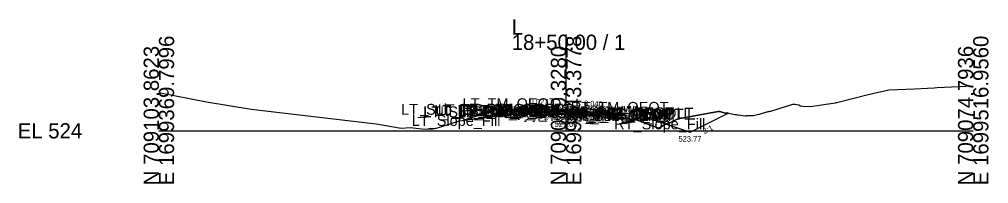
# Model space of a CAD drawing. Extents: x -63 to 1153, y -24 to 9522.
# Drawn here: x 974.3 to 1152.8, y 490.3 to 520.5 of the extents above; entities that cross this region are included whole.
import ezdxf

# ---------------------------------------------------------------- set-up
doc = ezdxf.new("R2010")
doc.units = 0
for name, color, linetype in [('Default', 7, 'Continuous'), ('Exist Cross Section Cell', 7, 'Continuous'), ('Exist XS Center Line Elevation Label', 7, 'Continuous'), ('Exist XS Ground Line', 7, 'Continuous'), ('Prop CMT DNC', 7, 'Continuous'), ('Prop CMT Pvmt Course 1', 7, 'Continuous'), ('Prop CMT Pvmt Course 2', 7, 'Continuous'), ('Prop CMT Pvmt Surface', 7, 'Continuous'), ('Prop CMT Pvmt Surface Overlay', 7, 'Continuous'), ('Prop CMT Pvmt Surface Shoulder', 7, 'Continuous'), ('Prop CMT Shld Paved Course 1', 7, 'Continuous'), ('Prop CMT Shld Paved Course 2', 7, 'Continuous'), ('Prop CMT Slope Grass', 7, 'Continuous'), ('Prop CMT Subgrade Earthwork', 7, 'Continuous'), ('Prop XS Ditch Standard Text', 7, 'Continuous'), ('Prop XS Earthwork Shape', 7, 'Continuous'), ('Prop XS EOT Tick Mark', 7, 'Continuous'), ('Prop XS SE Text', 7, 'Continuous'), ('Prop XS Side Slope Text', 7, 'Continuous')]:
    doc.layers.add(name, color=color, linetype=linetype)

msp = doc.modelspace()

# ---------------------------------------------------------------- linework, layer by layer
at = {"layer": 'Exist Cross Section Cell'}
for p, q in [((1075, 500), (1075, 517.67)), ((1000, 500), (1075, 500)), ((1075, 500), (1150, 500))]:
    msp.add_line(p, q, dxfattribs=at)
at = {"layer": 'Exist XS Ground Line'}
msp.add_lwpolyline([(1000, 507.05), (1008.75, 505.31), (1017.01, 503.98), (1040, 501.31), (1044.65, 500.47), (1046.27, 500.59), (1048.41, 500.39), (1050.28, 500.29), (1051.78, 500.66), (1055.36, 501.81), (1063.63, 502.9), (1064.17, 502.95), (1064.63, 503.02), (1064.89, 503.02), (1074.38, 503.08), (1074.84, 503.05), (1075, 503.03), (1083.86, 502.39), (1084.58, 502.31), (1088.01, 502), (1090.71, 500.95), (1092.1, 500.48), (1093.17, 501.19), (1094.23, 501.54), (1095.33, 502.06), (1095.52, 502.13), (1095.77, 502.2), (1095.96, 502.24), (1103.04, 503.52), (1103.27, 503.55), (1104.39, 503.22), (1104.68, 503.28), (1106.09, 503.02), (1106.31, 503), (1106.51, 502.96), (1106.7, 502.96), (1108.02, 502.77), (1108.11, 502.77), (1108.19, 502.77), (1108.26, 502.77), (1108.34, 502.79), (1109.45, 502.8), (1109.47, 502.8), (1109.49, 502.81), (1109.51, 502.81), (1110.51, 503.05), (1110.55, 503.06), (1110.58, 503.06), (1110.63, 503.07), (1111.96, 503.46), (1112.1, 503.49), (1112.25, 503.53), (1112.4, 503.56), (1112.56, 503.6), (1112.75, 503.63), (1116.8, 504.91), (1117.2, 504.87), (1117.54, 504.86), (1117.87, 504.75), (1118.21, 504.62), (1118.58, 504.53), (1118.91, 504.44), (1120.48, 504.53), (1122.07, 504.78), (1124.61, 505.16), (1124.72, 505.18), (1124.86, 505.21), (1130.43, 506.63), (1134.49, 507.55), (1139.19, 507.71), (1141.56, 507.85), (1142.81, 507.87), (1143.39, 507.98), (1150, 508.25)], dxfattribs=at)
at = {"layer": 'Prop CMT Pvmt Course 1'}
for points in [[(1075, 503.71), (1065, 503.98)], [(1065, 503.98), (1065, 503.73)], [(1065, 503.73), (1075, 503.46)], [(1075, 503.58), (1075, 503.71)], [(1075, 503.71), (1085, 503.31)], [(1075, 503.58), (1075, 503.71)], [(1075, 503.46), (1075, 503.58), (1075, 503.58)], [(1075, 503.46), (1075, 503.58), (1075, 503.58)], [(1085, 503.06), (1075, 503.46)], [(1085, 503.31), (1085, 503.06)]]:
    msp.add_lwpolyline(points, dxfattribs=at)
at = {"layer": 'Prop CMT Pvmt Course 2'}
for points in [[(1075, 503.46), (1065, 503.73)], [(1065, 503.73), (1065, 503.48)], [(1065, 503.48), (1075, 503.21)], [(1075, 503.21), (1075, 503.46)], [(1075, 503.21), (1075, 503.46)], [(1075, 503.46), (1085, 503.06)], [(1085, 502.81), (1075, 503.21)], [(1085, 503.06), (1085, 502.81)]]:
    msp.add_lwpolyline(points, dxfattribs=at)
at = {"layer": 'Prop CMT Pvmt Surface'}
for points in [[(1075, 503.71), (1065, 503.98)], [(1075, 503.71), (1085, 503.31)]]:
    msp.add_lwpolyline(points, dxfattribs=at)
at = {"layer": 'Prop CMT Pvmt Surface Overlay'}
for points in [[(1075, 503.71), (1065, 503.98)], [(1075, 503.71), (1085, 503.31)]]:
    msp.add_lwpolyline(points, dxfattribs=at)
at = {"layer": 'Prop CMT Pvmt Surface Shoulder'}
for points in [[(1065, 503.98), (1064.99, 503.98)], [(1085, 503.31), (1085.01, 503.31)]]:
    msp.add_lwpolyline(points, dxfattribs=at)
at = {"layer": 'Prop CMT Shld Paved Course 1'}
for points in [[(1065, 503.98), (1064.99, 503.98), (1064.75, 503.74)], [(1064.75, 503.74), (1065, 503.73)], [(1065, 503.73), (1065, 503.98)], [(1085, 503.31), (1085.01, 503.31), (1085.27, 503.04)], [(1085, 503.06), (1085, 503.31)], [(1085.27, 503.04), (1085, 503.06)]]:
    msp.add_lwpolyline(points, dxfattribs=at)
at = {"layer": 'Prop CMT Shld Paved Course 2'}
for points in [[(1064.75, 503.74), (1064.5, 503.49)], [(1064.5, 503.49), (1065, 503.48)], [(1065, 503.73), (1064.75, 503.74)], [(1064.75, 503.74), (1064.75, 503.74)], [(1065, 503.48), (1065, 503.73)], [(1085, 503.06), (1085.27, 503.04)], [(1085, 502.81), (1085, 503.06)], [(1085.53, 502.78), (1085, 502.81)], [(1085.27, 503.04), (1085.27, 503.04)], [(1085.27, 503.04), (1085.53, 502.78)]]:
    msp.add_lwpolyline(points, dxfattribs=at)
at = {"layer": 'Prop CMT Slope Grass'}
for points in [[(1062, 503.88), (1056.05, 501.9)], [(1064.99, 503.98), (1062, 503.88)], [(1085.01, 503.31), (1088, 503.07)], [(1088, 503.07), (1097.89, 499.77), (1104.84, 503.25)]]:
    msp.add_lwpolyline(points, dxfattribs=at)
at = {"layer": 'Prop CMT Subgrade Earthwork'}
for points in [[(1064.5, 503.49), (1064.05, 503.95)], [(1065, 503.48), (1064.5, 503.49)], [(1075, 503.21), (1065, 503.48)], [(1075, 503.21), (1085, 502.81)], [(1085, 502.81), (1085.53, 502.78)], [(1085.53, 502.78), (1085.97, 503.23)]]:
    msp.add_lwpolyline(points, dxfattribs=at)
at = {"layer": 'Prop XS Earthwork Shape'}
for points in [[(1085, 502.81), (1085.53, 502.78), (1085.97, 503.23), (1088, 503.07), (1093.4, 501.27), (1093.17, 501.19), (1092.1, 500.48), (1090.71, 500.95), (1088.01, 502), (1084.58, 502.31), (1083.86, 502.39), (1075, 503.03), (1074.84, 503.05), (1074.38, 503.08), (1064.89, 503.02), (1064.63, 503.02), (1064.17, 502.95), (1063.63, 502.9), (1056.05, 501.9), (1062, 503.88), (1064.05, 503.95), (1064.5, 503.49), (1065, 503.48), (1075, 503.21)], [(1097.89, 499.77), (1104.84, 503.25), (1104.68, 503.28), (1104.39, 503.22), (1103.27, 503.55), (1103.04, 503.52), (1095.96, 502.24), (1095.77, 502.2), (1095.52, 502.13), (1095.33, 502.06), (1094.23, 501.54), (1093.4, 501.27)]]:
    msp.add_lwpolyline(points, close=True, dxfattribs=at)
at = {"layer": 'Prop XS EOT Tick Mark'}
for points in [[(1065, 503.98), (1065, 504.98)], [(1085, 503.31), (1085, 504.31)]]:
    msp.add_lwpolyline(points, dxfattribs=at)

# ---------------------------------------------------------------- texts
at = {"layer": 'Default'}
msp.add_text('-', height=0.0001, dxfattribs=at).set_placement((1000, 500))
at = {"layer": 'Exist Cross Section Cell'}
for s, p in [('L', (1065, 517.67)), ('18+50.00 / 1', (1065, 514.87)), ('EL 524', (974, 498.6))]:
    msp.add_text(s, height=2.8, dxfattribs=at).set_placement(p)
for s, p in [('E 1699369.7996', (1002.8, 490)), ('E 1699443.3778', (1077.8, 490)), ('E 1699516.9560', (1152.8, 490)), ('N 709103.8623', (1000, 490)), ('N 709089.3280', (1075, 490)), ('N 709074.7936', (1150, 490))]:
    msp.add_text(s, height=2.8, rotation=90, dxfattribs=at).set_placement(p)
at = {"layer": 'Exist XS Center Line Elevation Label'}
msp.add_text('527.03', height=1, dxfattribs=at).set_placement((1072.88, 500.7))
at = {"layer": 'Prop CMT DNC'}
for s, p in [('LT_TM_OEOT', (1055.94, 503.98)), ('RT_TM_OEOT', (1075.9, 503.31)), ('LT_Sub_Trench_Out_DLT', (1044.61, 502.95)), ('LT_Sub_Trench_Out', (1048.71, 502.49)), ('LT_PS2_Shelf_Out', (1050.73, 502.74)), ('LT_GS_OS_CTL', (1051.37, 502.88)), ('LT_PS2_OEOP', (1054.98, 502.74)), ('LT_Sub_OEOT', (1055.08, 502.48)), ('LT_PV2_OEOT', (1055.17, 502.73)), ('LT_PV1_OEOT', (1055.74, 502.98)), ('LT_PS1_OEOP', (1055.79, 502.98)), ('RT_PV1_OEEOP_W', (1062.94, 502.58)), ('LT_PV1_OEEOP_W', (1062.98, 502.58)), ('RT_Sub_OEEOP', (1064.17, 502.21)), ('LT_Sub_OEEOP', (1064.21, 502.21)), ('RT_PV2_OEEOP', (1064.26, 502.46)), ('LT_PV2_OEEOP', (1064.31, 502.46)), ('RT_Sub_Trench_Out_DLT', (1066.49, 502.23)), ('PV1_PGL_W', (1067.58, 502.58)), ('PV1_PGL', (1069.47, 502.71)), ('RT_Sub_Trench_Out', (1069.69, 501.78)), ('RT_PS2_Shelf_Out', (1071.21, 502.04)), ('RT_Sub_OEOT', (1075.03, 501.81)), ('RT_PV2_OEOT', (1075.13, 502.06)), ('RT_PS2_OEOP', (1075.46, 502.04)), ('RT_PV1_OEOT', (1075.69, 502.31)), ('RT_PS1_OEOP', (1075.77, 502.31)), ('RT_GS_OS_CTL', (1077.32, 502.07)), ('LT_Slope_Fill', (1046.57, 500.9)), ('RT_Slope_Fill', (1083.87, 500.27))]:
    msp.add_text(s, height=2, dxfattribs=at).set_placement(p)
at = {"layer": 'Prop XS Ditch Standard Text'}
msp.add_text('523.77', height=1, dxfattribs=at).set_placement((1095.72, 498.02))
msp.add_text('523.77', height=1, dxfattribs=at).set_placement((1095.72, 498.02))
at = {"layer": 'Prop XS SE Text'}
for s, rotation, p in [('0.027', 358.4248, (1068.27, 504.89)), ('0.040', 357.7094, (1078.29, 504.57))]:
    msp.add_text(s, height=1, rotation=rotation, dxfattribs=at).set_placement(p)
at = {"layer": 'Prop XS Side Slope Text'}
for s, rotation, p in [('3:1', 18.4332, (1058.04, 503.35)), ('3:1', 341.5652, (1090.18, 503.13)), ('2:1', 26.5651, (1100.49, 499.36)), ('2:1', 26.5651, (1100.49, 499.36))]:
    msp.add_text(s, height=1, rotation=rotation, dxfattribs=at).set_placement(p)

doc.saveas('drawing.dxf')
